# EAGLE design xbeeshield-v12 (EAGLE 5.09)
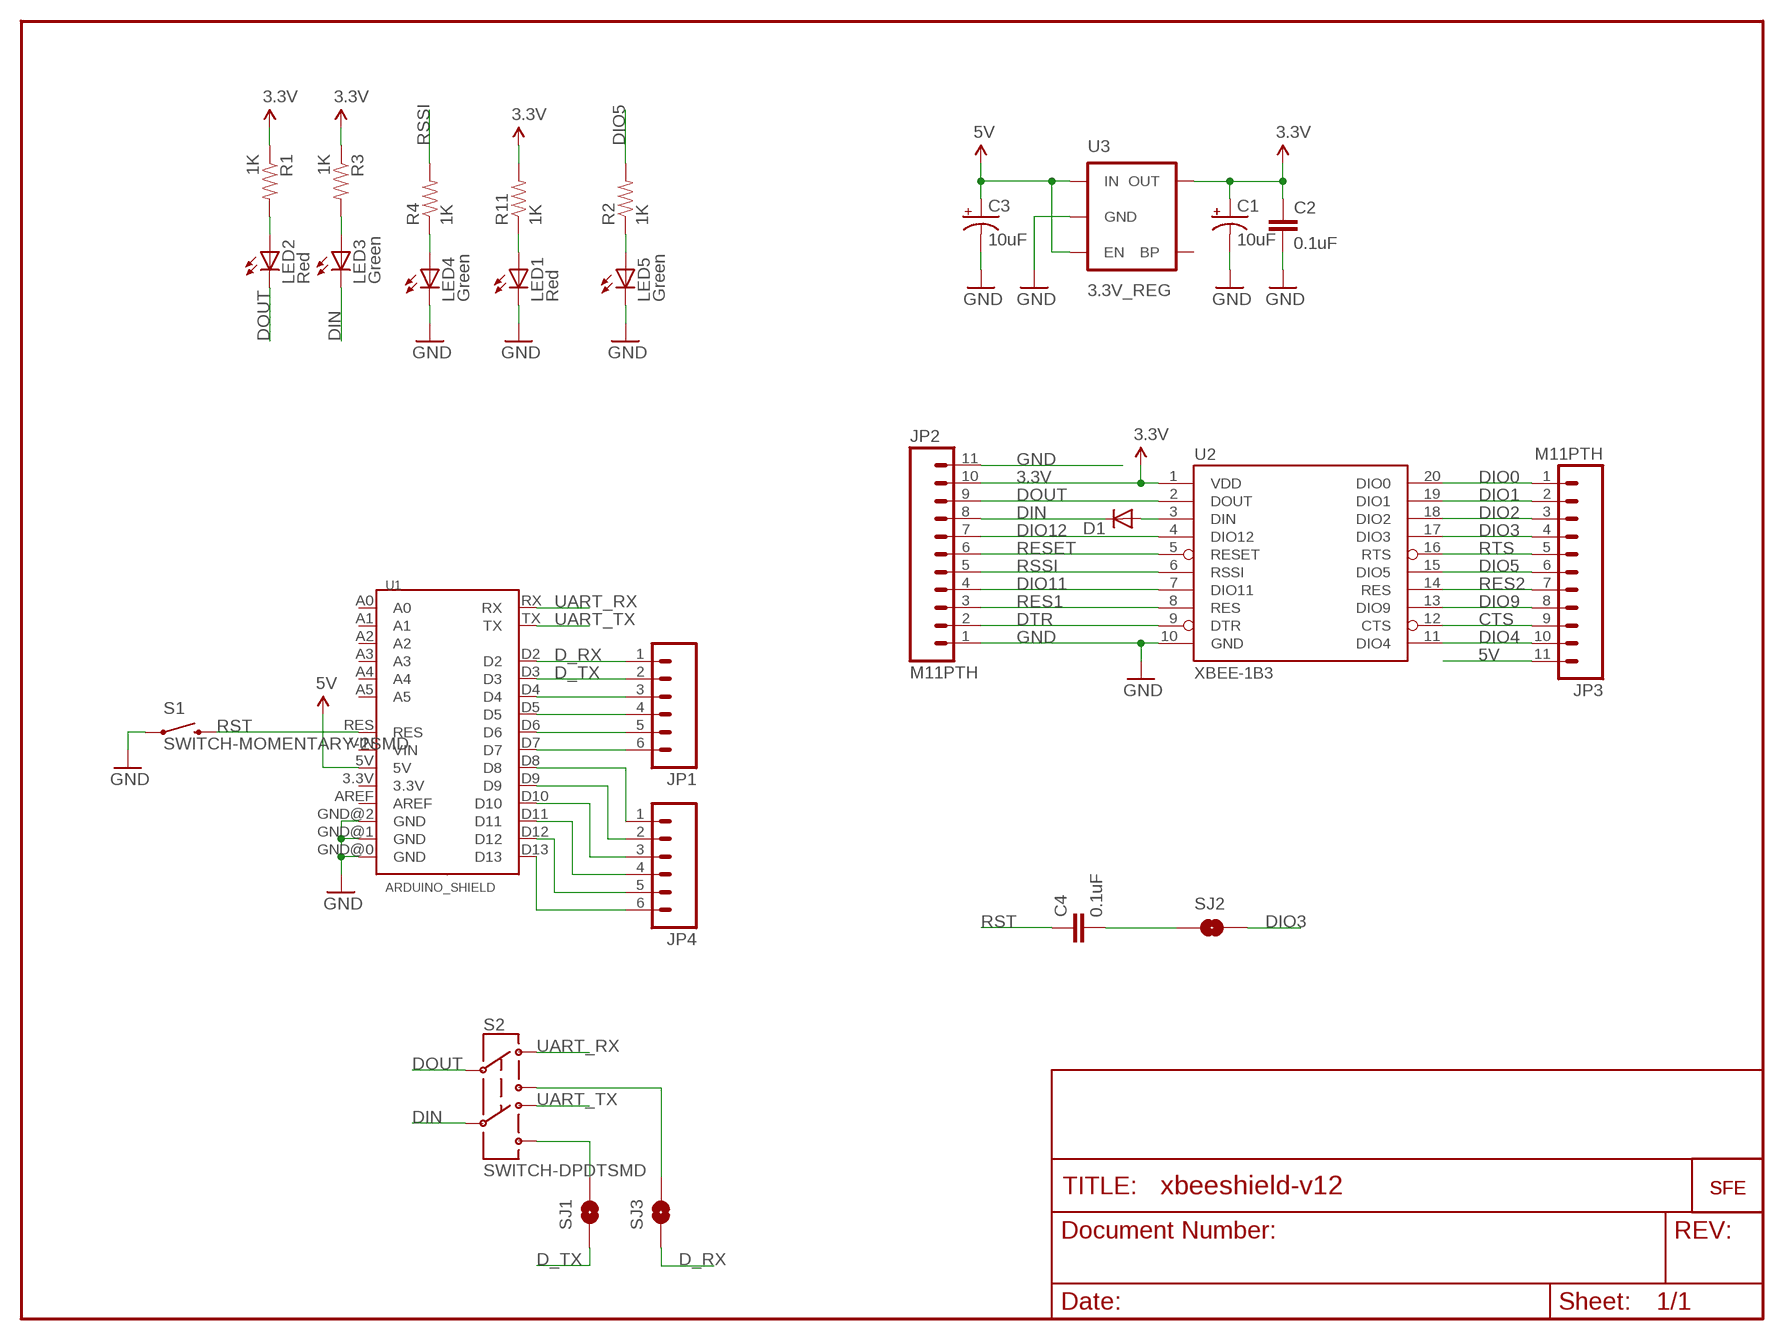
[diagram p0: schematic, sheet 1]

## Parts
C1  10uF  CAP_POL1206  [EIA3216]
C2  0.1uF  CAP0402-CAP  [0402-CAP]
C3  10uF  CAP_POL1206  [EIA3216]
C4  0.1uF  CAP0402-CAP  [0402-CAP]
D1  DIODESOD  [SOD-323]
JP1  M06SIP  [1X06]
JP2  M11PTH  [1X11]
JP3  M11PTH  [1X11]
JP4  M06SIP  [1X06]
LED1  Red  LED0603  [LED-0603]
LED2  Red  LED0603  [LED-0603]
LED3  Green  LED0603  [LED-0603]
LED4  Green  LED0603  [LED-0603]
LED5  Green  LED0603  [LED-0603]
R1  1K  RESISTOR0402-RES  [0402-RES]
R2  1K  RESISTOR0402-RES  [0402-RES]
R3  1K  RESISTOR0402-RES  [0402-RES]
R4  1K  RESISTOR0402-RES  [0402-RES]
R11  1K  RESISTOR0402-RES  [0402-RES]
S1  SWITCH-MOMENTARY-2SMD  [TACTILE_SWITCH_SMD]
S2  SWITCH-DPDTSMD  [AYZ0202]
SJ1  D_TX  SOLDERJUMPERNC  [SJ_2S]
SJ2  SOLDERJUMPERTRACE  [SJ_2S-TRACE]
SJ3  D_RX  SOLDERJUMPERNC  [SJ_2S]
U1  ARDUINO_SHIELD  [DUEMILANOVE_SHIELD]
U2  XBEE-1B3  [XBEE-SMD]
U3  3.3V_REG  V_REG_LDOSMD  [SOT23-5]
U$1  LOGO-SFESK  [SFE-LOGO-FLAME]
U$4  LOGO-SFENEW  [SFE-NEW-WEBLOGO]

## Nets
3.3V: C1.A(+) C2.1 JP2.10 R1.1 R3.1 R11.2 U2.1(VDD) U3.5(OUT)
5V: C3.A(+) JP3.11 U1.5V U3.1(IN) U3.3(EN)
CTS: JP3.9 U2.12(CTS)
D_RX: JP1.1 SJ3.1 U1.D2
D_TX: JP1.2 SJ1.1 U1.D3
DIN: D1.1(C) JP2.8 LED3.C S2.5
DIO0: JP3.1 U2.20(DIO0)
DIO1: JP3.2 U2.19(DIO1)
DIO2: JP3.3 U2.18(DIO2)
DIO3: JP3.4 SJ2.2 U2.17(DIO3)
DIO4: JP3.10 U2.11(DIO4)
DIO5: JP3.6 R2.2 U2.15(DIO5)
DIO9: JP3.8 U2.13(DIO9)
DIO11: JP2.4 U2.7(DIO11)
DIO12: JP2.7 U2.4(DIO12)
DOUT: JP2.9 LED2.C S2.2 U2.2(DOUT)
DTR: JP2.2 U2.9(DTR)
GND: C1.C(-) C2.2 C3.C(-) JP2.1 JP2.11 LED1.C LED4.C LED5.C S1.1 U1.GND@0(GND) U1.GND@1(GND) U1.GND@2(GND) U2.10(GND) U3.2(GND)
N$1: LED2.A R1.2
N$2: LED4.A R4.1
N$3: D1.2(A) U2.3(DIN)
N$4: LED3.A R3.2
N$5: C4.2 SJ2.1
N$17: JP4.1 U1.D8
N$18: JP4.2 U1.D9
N$30: JP4.3 U1.D10
N$38: LED1.A R11.1
N$43: JP4.4 U1.D11
N$55: JP4.5 U1.D12
N$67: JP4.6 U1.D13
N$139: LED5.A R2.1
N$140: S2.6 SJ1.2
N$141: S2.3 SJ3.2
N$142: JP1.3 U1.D4
N$143: JP1.4 U1.D5
N$144: JP1.5 U1.D6
N$145: JP1.6 U1.D7
RES1: JP2.3 U2.8(RES)
RES2: JP3.7 U2.14(RES)
RESET: JP2.6 U2.5(RESET)
RSSI: JP2.5 R4.2 U2.6(RSSI)
RST: C4.1 S1.3 U1.RES
RTS: JP3.5 U2.16(RTS)
UART_RX: S2.1 U1.RX
UART_TX: S2.4 U1.TX
Unconnected: U1.3.3V U1.A0 U1.A1 U1.A2 U1.A3 U1.A4 U1.A5 U1.AREF U1.VIN U3.4(BP)

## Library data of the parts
C1 C3 = SparkFun:CAP_POL: Capacitor Polarized
C2 C4 = SparkFun:CAP: Capacitor
D1 = SparkFun:DIODE: Diode
JP1 JP4 = SparkFun:M06: Header 6 Standard 6-pin 0.1" header. Use with straight break away headers (SKU : PRT-00116), right angle break away headers (PRT-00553), swiss pins (PRT-00743), machine pins (PRT-00117), and female headers (PRT-00115). Molex polarized connector foot print use with SKU : PRT-08094 with associated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
JP2 JP3 = SparkFun:M11: Header 11 Standard 11-pin 0.1" header. Use with straight break away headers (SKU : PRT-00116), right angle break away headers (PRT-00553), swiss pins (PRT-00743), machine pins (PRT-00117), and female headers (PRT-00115).
LED1-LED5 = SparkFun:LED: LEDs
R1-R4 R11 = SparkFun:RESISTOR: Resistor
S1 = SparkFun:SWITCH-MOMENTARY-2
S2 = SparkFun:SWITCH-DPDT: DPDT Version of the COM-00597
SJ1-SJ3 = SparkFun:SOLDERJUMPER: Solder Jumper
U1 = SparkFun:ARDUINO_SHIELD
U2 = SparkFun:XBEE-1
U3 = SparkFun:V_REG_LDO: Voltage Regulator LDO Standard 150mA LDO voltage regulator in SOT-23 layout. Micrel part MIC5205. BP (by-pass) pin is used to lower output noise with 470pF cap.
U$1 U$4 = SparkFun:LOGO-SFE: Spark Fun Electronics PCB Logo

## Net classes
0 default: width 0.203 mm
1 vcc: width 0.305 mm

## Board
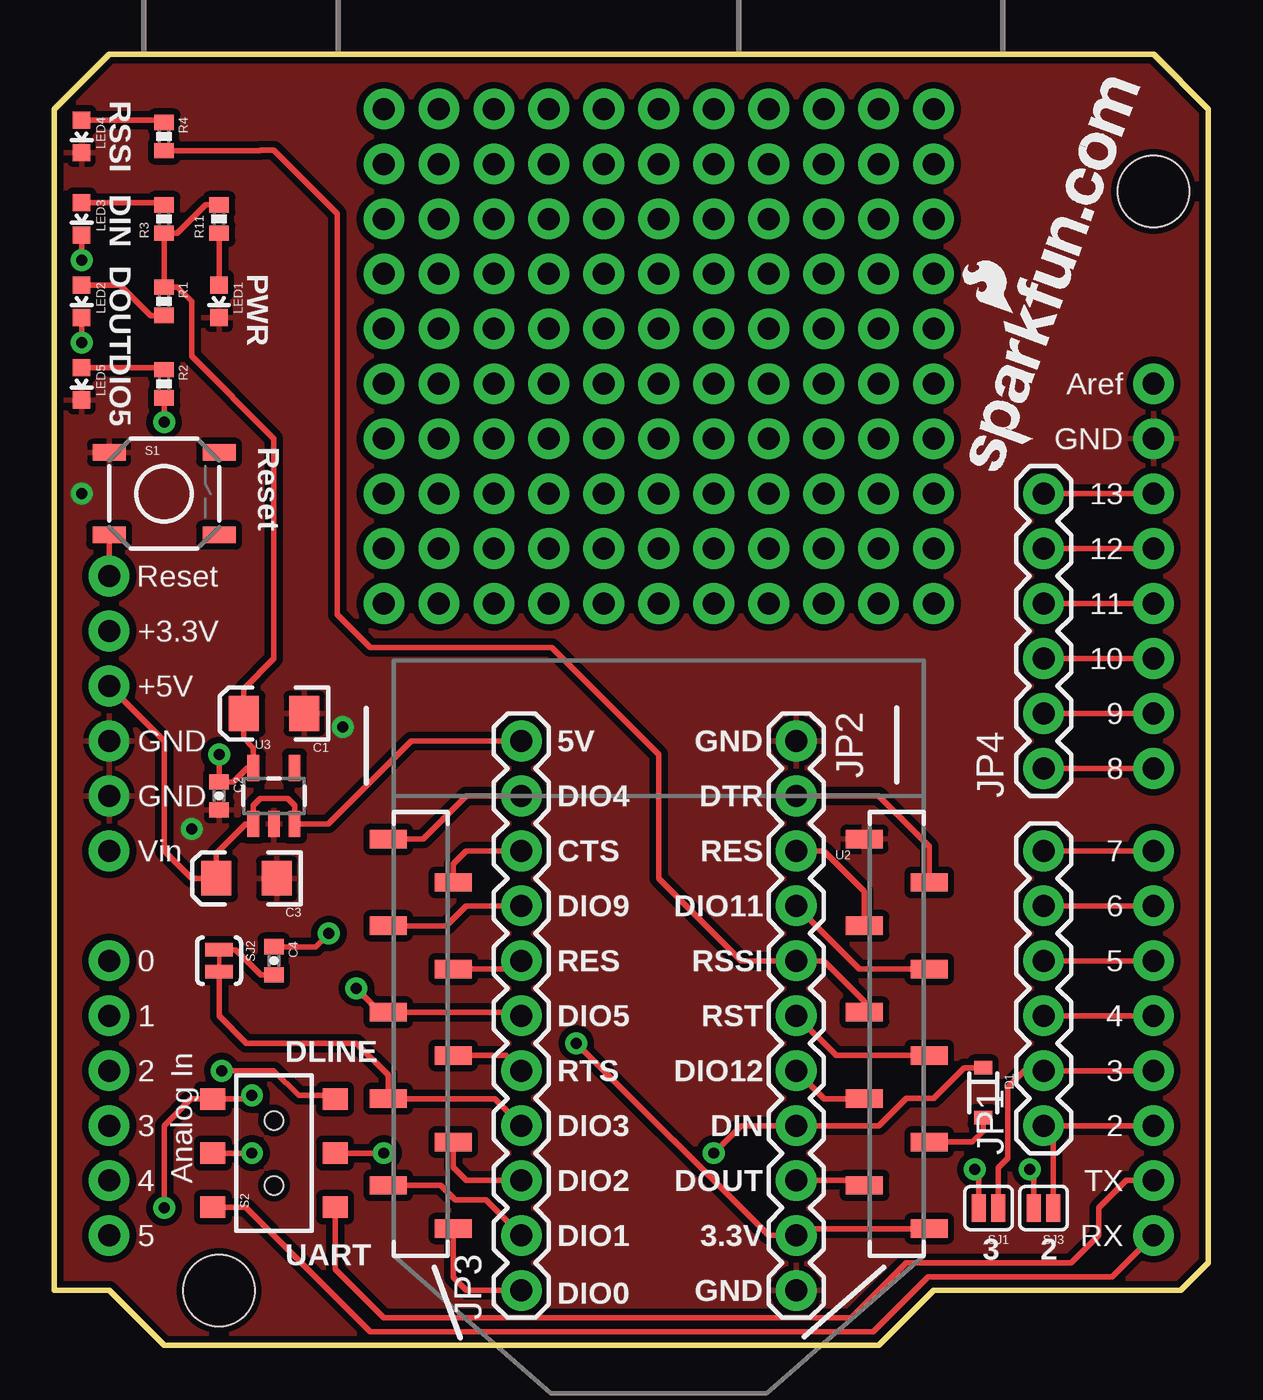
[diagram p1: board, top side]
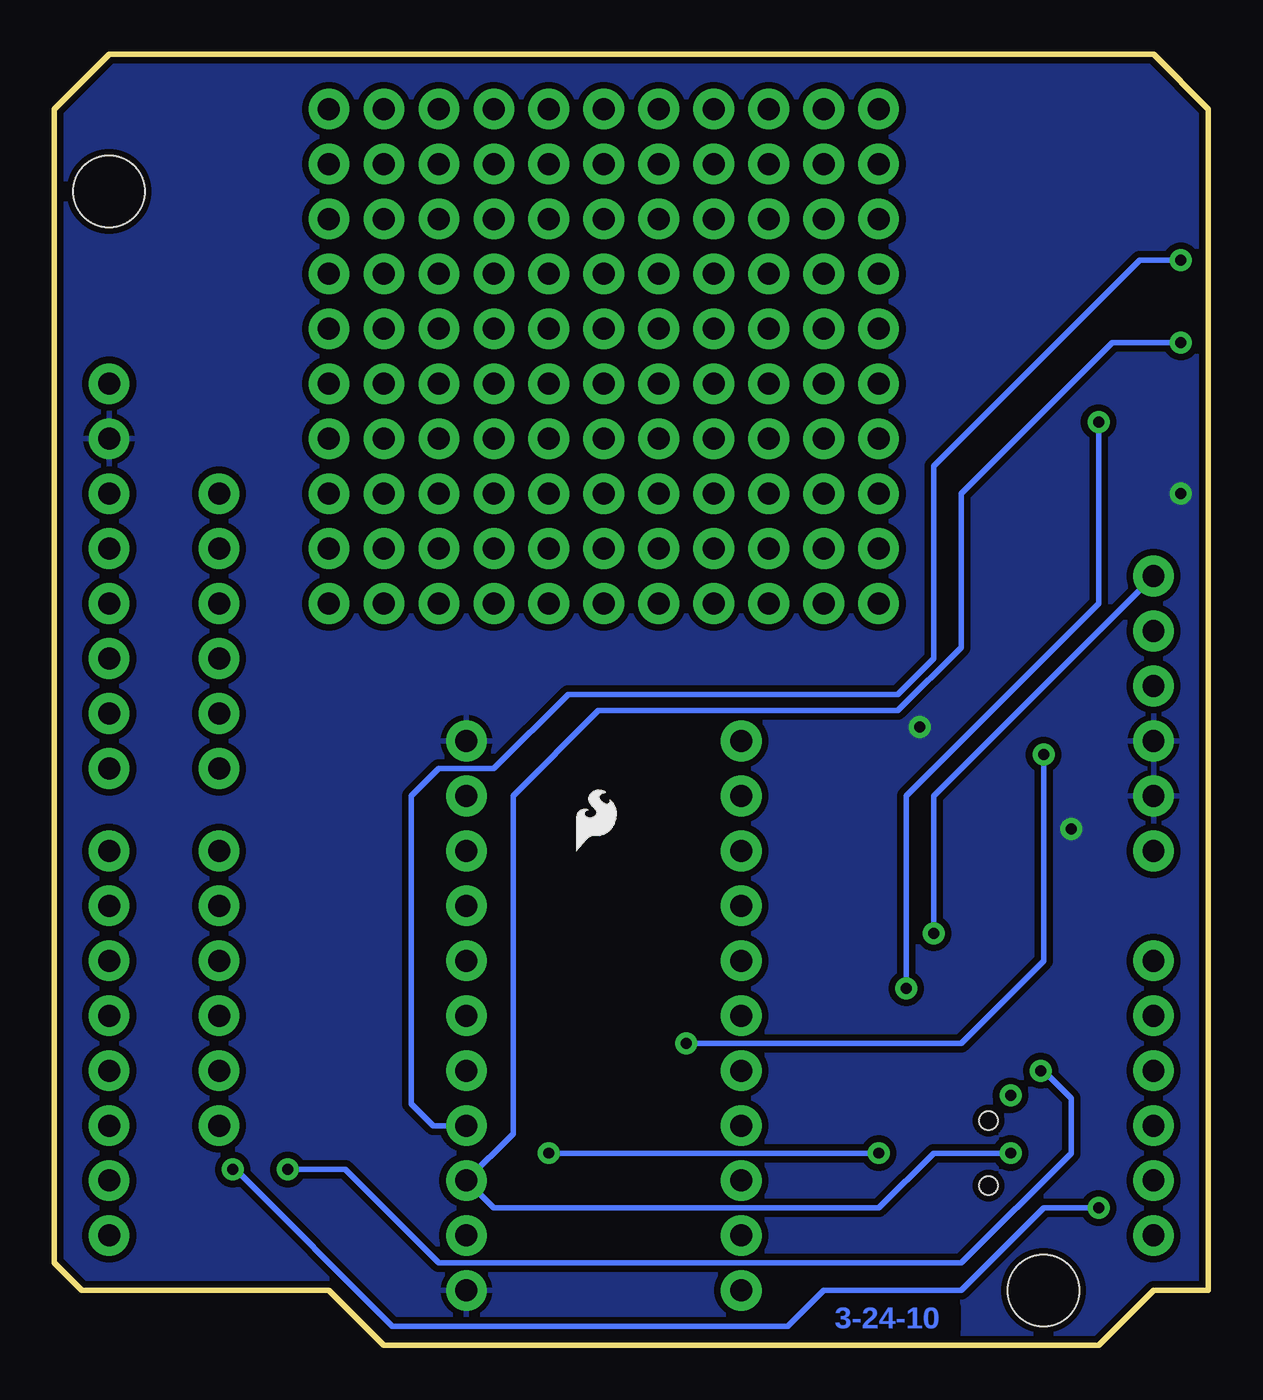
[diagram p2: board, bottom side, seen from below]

Size 53.34 x 59.69 mm. Coordinates in mm from the lower left corner, seen from the top.
Outline: 0,2.54 0,57.15 2.54,59.69 50.8,59.69 53.34,57.15 53.34,3.81 52.07,2.54 40.64,2.54 38.1,0 5.08,0 2.54,2.54 0,2.54
Copper layers (1*16): Top 0.035mm / dielectric 1.5mm / Bottom 0.035mm
Design rules "SparkFun": minimum track width 8mil, minimum drill 20mil, track to track 8mil, track to pad 8mil, pad to pad 8mil, via to via 8mil, smd to smd 8mil, copper to edge 8mil, drill to drill 8mil, minimum pad ring 12mil, minimum via ring 10mil, stop-mask expansion 4mil, vias tented up to drill 20mil, thermal gap 10mil

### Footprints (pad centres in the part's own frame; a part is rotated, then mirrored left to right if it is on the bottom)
EIA3216 = smd 1.4 x 1.6: A 1.4,0; C -1.4,0
0402-CAP = smd 0.7 x 0.9: 1 -0.65,0; 2 0.65,0
SOD-323 = smd 0.63 x 0.83: 1 -1.15,0; 2 1.15,0
1X06 = drill 1.016 pad 1.88 round: 1 0,0; 2 2.54,0; 3 5.08,0; 4 7.62,0; 5 10.16,0; 6 12.7,0
1X11 = drill 1.016 pad 1.88 round: 1 0,0; 2 2.54,0; 3 5.08,0; 4 7.62,0; 5 10.16,0; 6 12.7,0; 7 15.24,0; 8 17.78,0; 9 20.32,0; 10 22.86,0; 11 25.4,0
LED-0603 = smd 0.8 x 0.8: A 0,-0.75; C 0,0.75
0402-RES = smd 0.7 x 0.9: 1 -0.65,0; 2 0.65,0
TACTILE_SWITCH_SMD = smd 1.524 x 0.762: 1 -2.54,1.905; 2 2.54,1.905; 3 -2.54,-1.905; 4 2.54,-1.905
AYZ0202 = smd 1 x 1.15: 1 -2.5,2.825; 2 0,2.825; 3 2.5,2.825; 4 -2.5,-2.825; 5 0,-2.825; 6 2.5,-2.825 | hole 0.85: 1.5,0; -1.5,0
SJ_2S = smd 0.635 x 1.27: 1 -0.45,0; 2 0.45,0
SJ_2S-TRACE = smd 0.635 x 1.27: 1 -0.508,0; 2 0.508,0
DUEMILANOVE_SHIELD = drill 1.016 pad 1.88 round: 3.3V 50.8,26.67; 5V 50.8,29.21; A0 50.8,41.91; A1 50.8,44.45; A2 50.8,46.99; A3 50.8,49.53; A4 50.8,52.07; A5 50.8,54.61; AREF 2.54,15.24; D2 2.54,49.53; D3 2.54,46.99; D4 2.54,44.45; D5 2.54,41.91; D6 2.54,39.37; D7 2.54,36.83; D8 2.54,33.02; D9 2.54,30.48; D10 2.54,27.94; D11 2.54,25.4; D12 2.54,22.86; D13 2.54,20.32; GND@0 50.8,31.75; GND@1 50.8,34.29; GND@2 2.54,17.78; RES 50.8,24.13; RX 2.54,54.61; TX 2.54,52.07; VIN 50.8,36.83 | hole 3.302: 45.72,57.15; 2.54,6.35
XBEE-SMD = smd 1.7 x 0.85: 1 -12.5,20; 2 -9.5,18; 3 -12.5,16; 4 -9.5,14; 5 -12.5,12; 6 -9.5,10; 7 -12.5,8; 8 -9.5,6; 9 -12.5,4; 10 -9.5,2; 11 12.5,2; 12 9.5,4; 13 12.5,6; 14 9.5,8; 15 12.5,10; 16 9.5,12; 17 12.5,14; 18 9.5,16; 19 12.5,18; 20 9.5,20
SOT23-5 = smd 0.55 x 1.2: 1 -0.95,-1.3; 2 0,-1.3; 3 0.95,-1.3; 4 0.95,1.3; 5 -0.95,1.3

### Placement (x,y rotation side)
C1  10.16,29.21 180 top
C2  7.62,25.4 270 top
C3  8.89,21.59 180 top
C4  10.16,17.78 270 top
D1  42.93,11.68 270 top
JP1  45.72,10.16 90 top
JP2  34.29,27.94 270 top
JP3  21.59,2.54 90 top
JP4  45.72,26.67 90 top
LED1  7.62,48.26 180 top
LED2  1.27,48.26 180 top
LED3  1.27,52.07 180 top
LED4  1.27,55.88 180 top
LED5  1.27,44.45 180 top
R1  5.08,48.26 270 top
R2  5.08,44.45 270 top
R3  5.08,52.07 90 top
R4  5.08,55.88 270 top
R11  7.62,52.07 90 top
S1  5.08,39.37 0 top
S2  10.16,8.89 90 top
SJ1  43.18,6.35 180 top
SJ2  7.62,17.78 270 top
SJ3  45.72,6.35 180 top
U1  53.34,59.69 180 top
U2  27.94,25.4 180 top
U3  10.16,25.4 0 top
U$1  29.21,22.86 0 bottom
U$4  44.54,39.97 70 top

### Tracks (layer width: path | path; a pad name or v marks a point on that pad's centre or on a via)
3.3V  (via drill 0.51)
  Top 0.254: R11.2 7,52.72 5.7,51.42 R3.1 R1.1 5.7,48.91 6.35,48.26 6.35,45.72 10.16,41.91 10.16,31.75 8.76,30.35 C1.A 8.76,28.07 9.21,27.62 U3.5 8.92,26.7 8.27,26.05 C2.1 v7.62,27.3 | U2.1 34.61,5.4 JP2.10 33.02,5.08 v24.13,13.97
  Bottom 0.254: v24.13,13.97 11.43,13.97 7.62,17.78 v7.62,27.3
5V
  Top 0.254: U1.5V 5.08,27.94 5.08,22.86 6.35,21.59 C3.A 7.49,22.73 8.86,24.1 U3.1 9.21,24.96 9.53,25.27 10.79,25.27 11.11,24.96 U3.3 12.67,24.1 16.51,27.94 JP3.11
CTS
  Top 0.254: U2.12 18.44,22.25 19.05,22.86 JP3.9
D_RX
  Top 0.254: U1.D2 JP1.1 46.17,9.71 SJ3.1
D_TX
  Top 0.254: U1.D3 JP1.2 44.83,12.7 44.07,11.94 44.07,8.64 43.63,8.2 SJ1.1
DIN  (via drill 0.51)
  Top 0.254: v1.27,50.16 LED3.C | D1.1 42.04,12.83 40.64,11.43 39.37,11.43 38.1,10.16 JP2.8 31.75,10.16 v30.48,8.89 | S2.5 v15.24,8.89
  Bottom 0.254: v1.27,50.16 3.17,50.16 12.7,40.64 12.7,31.75 14.35,30.1 29.59,30.1 33.02,26.67 35.56,26.67 36.83,25.4 36.83,11.18 35.81,10.16 JP2.8 | v15.24,8.89 v30.48,8.89
DIO0
  Top 0.254: U2.20 18.44,3.15 19.05,2.54 JP3.1
DIO1
  Top 0.254: JP3.2 19.94,6.73 18.54,6.73 17.87,7.4 U2.19
DIO2
  Top 0.254: U2.18 18.44,8.23 19.05,7.62 JP3.3
DIO3
  Top 0.254: JP3.4 20.35,11.4 U2.17 15.44,12.5 13.97,13.97 8.89,13.97 7.62,15.24 SJ2.2
DIO4
  Top 0.254: U2.11 17.05,23.4 19.05,25.4 JP3.10
DIO5  (via drill 0.51)
  Top 0.254: v5.08,42.67 R2.2 | JP3.6 21.43,15.4 U2.15 15.08,15.4 v13.97,16.51
  Bottom 0.254: v13.97,16.51 13.97,25.4 5.08,34.29 v5.08,42.67
DIO9
  Top 0.254: U2.13 18.13,19.4 19.05,20.32 JP3.8
DIO11
  Top 0.254: U2.7 37.21,17.4 JP2.4
DIO12
  Top 0.254: U2.4 35.59,11.4 JP2.7
DOUT  (via drill 0.51)
  Top 0.254: v1.27,46.35 LED2.C | JP2.9 37.22,7.62 U2.2 | S2.2 v9.14,8.89
  Bottom 0.254: v1.27,46.35 4.45,46.35 11.43,39.37 11.43,32.26 14.35,29.34 28.19,29.34 32.13,25.4 32.13,9.78 JP2.9 33.02,6.35 15.24,6.35 12.7,8.89 v9.14,8.89
DTR
  Top 0.254: JP2.2 38.1,25.4 40.44,23.06 U2.9
GND  (via drill 0.51)
  other vias: 1.27,39.37 6.35,23.88 13.34,28.57
  pour Top (isolate 0.305): 0,0 0,59.69 53.34,59.69 53.34,0
  pour Bottom (isolate 0.305): 0,59.69 0,0 53.34,0 53.34,59.69
N$1
  Top 0.254: LED2.A 3.06,49.01 4.46,47.61 R1.2
N$2
  Top 0.254: LED4.A 4.98,56.63 R4.1
N$3
  Top 0.254: U2.3 42.42,9.4 42.93,9.91 D1.2
N$4
  Top 0.254: LED3.A 4.98,52.82 R3.2
N$5
  Top 0.254: C4.2 9.54,17.13 8.38,18.29 SJ2.1
N$17
  Top 0.254: JP4.1 U1.D8
N$18
  Top 0.254: JP4.2 U1.D9
N$19  (via drill 1.02 pad 1.88)
  other vias: 40.64,34.29
N$20  (via drill 1.02 pad 1.88)
  other vias: 38.1,34.29
N$21  (via drill 1.02 pad 1.88)
  other vias: 35.56,34.29
N$22  (via drill 1.02 pad 1.88)
  other vias: 33.02,34.29
N$23  (via drill 1.02 pad 1.88)
  other vias: 30.48,34.29
N$24  (via drill 1.02 pad 1.88)
  other vias: 27.94,34.29
N$25  (via drill 1.02 pad 1.88)
  other vias: 25.4,34.29
N$26  (via drill 1.02 pad 1.88)
  other vias: 22.86,34.29
N$27  (via drill 1.02 pad 1.88)
  other vias: 20.32,34.29
N$28  (via drill 1.02 pad 1.88)
  other vias: 17.78,34.29
N$29  (via drill 1.02 pad 1.88)
  other vias: 15.24,34.29
N$30
  Top 0.254: JP4.3 U1.D10
N$31  (via drill 1.02 pad 1.88)
  other vias: 40.64,36.83
N$32  (via drill 1.02 pad 1.88)
  other vias: 38.1,36.83
N$33  (via drill 1.02 pad 1.88)
  other vias: 35.56,36.83
N$34  (via drill 1.02 pad 1.88)
  other vias: 33.02,36.83
N$35  (via drill 1.02 pad 1.88)
  other vias: 30.48,36.83
N$36  (via drill 1.02 pad 1.88)
  other vias: 27.94,36.83
N$37  (via drill 1.02 pad 1.88)
  other vias: 25.4,36.83
N$38
  Top 0.254: LED1.A R11.1
N$39  (via drill 1.02 pad 1.88)
  other vias: 22.86,36.83
N$40  (via drill 1.02 pad 1.88)
  other vias: 20.32,36.83
N$41  (via drill 1.02 pad 1.88)
  other vias: 17.78,36.83
N$42  (via drill 1.02 pad 1.88)
  other vias: 15.24,36.83
N$43
  Top 0.254: JP4.4 U1.D11
N$44  (via drill 1.02 pad 1.88)
  other vias: 40.64,39.37
N$45  (via drill 1.02 pad 1.88)
  other vias: 38.1,39.37
N$46  (via drill 1.02 pad 1.88)
  other vias: 35.56,39.37
N$47  (via drill 1.02 pad 1.88)
  other vias: 33.02,39.37
N$48  (via drill 1.02 pad 1.88)
  other vias: 30.48,39.37
N$49  (via drill 1.02 pad 1.88)
  other vias: 27.94,39.37
N$50  (via drill 1.02 pad 1.88)
  other vias: 25.4,39.37
N$51  (via drill 1.02 pad 1.88)
  other vias: 22.86,39.37
N$52  (via drill 1.02 pad 1.88)
  other vias: 20.32,39.37
N$53  (via drill 1.02 pad 1.88)
  other vias: 17.78,39.37
N$54  (via drill 1.02 pad 1.88)
  other vias: 15.24,39.37
N$55
  Top 0.254: JP4.5 U1.D12
N$56  (via drill 1.02 pad 1.88)
  other vias: 40.64,41.91
N$57  (via drill 1.02 pad 1.88)
  other vias: 38.1,41.91
N$58  (via drill 1.02 pad 1.88)
  other vias: 35.56,41.91
N$59  (via drill 1.02 pad 1.88)
  other vias: 33.02,41.91
N$60  (via drill 1.02 pad 1.88)
  other vias: 30.48,41.91
N$61  (via drill 1.02 pad 1.88)
  other vias: 27.94,41.91
N$62  (via drill 1.02 pad 1.88)
  other vias: 25.4,41.91
N$63  (via drill 1.02 pad 1.88)
  other vias: 22.86,41.91
N$64  (via drill 1.02 pad 1.88)
  other vias: 20.32,41.91
N$65  (via drill 1.02 pad 1.88)
  other vias: 17.78,41.91
N$66  (via drill 1.02 pad 1.88)
  other vias: 15.24,41.91
N$67
  Top 0.254: JP4.6 U1.D13
N$68  (via drill 1.02 pad 1.88)
  other vias: 40.64,44.45
N$69  (via drill 1.02 pad 1.88)
  other vias: 38.1,44.45
N$70  (via drill 1.02 pad 1.88)
  other vias: 35.56,44.45
N$71  (via drill 1.02 pad 1.88)
  other vias: 33.02,44.45
N$72  (via drill 1.02 pad 1.88)
  other vias: 30.48,44.45
N$73  (via drill 1.02 pad 1.88)
  other vias: 27.94,44.45
N$74  (via drill 1.02 pad 1.88)
  other vias: 25.4,44.45
N$75  (via drill 1.02 pad 1.88)
  other vias: 22.86,44.45
N$76  (via drill 1.02 pad 1.88)
  other vias: 20.32,44.45
N$77  (via drill 1.02 pad 1.88)
  other vias: 17.78,44.45
N$78  (via drill 1.02 pad 1.88)
  other vias: 15.24,44.45
N$80  (via drill 1.02 pad 1.88)
  other vias: 40.64,46.99
N$81  (via drill 1.02 pad 1.88)
  other vias: 38.1,46.99
N$82  (via drill 1.02 pad 1.88)
  other vias: 35.56,46.99
N$83  (via drill 1.02 pad 1.88)
  other vias: 33.02,46.99
N$84  (via drill 1.02 pad 1.88)
  other vias: 30.48,46.99
N$85  (via drill 1.02 pad 1.88)
  other vias: 27.94,46.99
N$86  (via drill 1.02 pad 1.88)
  other vias: 25.4,46.99
N$87  (via drill 1.02 pad 1.88)
  other vias: 22.86,46.99
N$88  (via drill 1.02 pad 1.88)
  other vias: 20.32,46.99
N$89  (via drill 1.02 pad 1.88)
  other vias: 17.78,46.99
N$90  (via drill 1.02 pad 1.88)
  other vias: 15.24,46.99
N$92  (via drill 1.02 pad 1.88)
  other vias: 40.64,49.53
N$93  (via drill 1.02 pad 1.88)
  other vias: 38.1,49.53
N$94  (via drill 1.02 pad 1.88)
  other vias: 35.56,49.53
N$95  (via drill 1.02 pad 1.88)
  other vias: 33.02,49.53
N$96  (via drill 1.02 pad 1.88)
  other vias: 30.48,49.53
N$97  (via drill 1.02 pad 1.88)
  other vias: 27.94,49.53
N$98  (via drill 1.02 pad 1.88)
  other vias: 25.4,49.53
N$99  (via drill 1.02 pad 1.88)
  other vias: 22.86,49.53
N$100  (via drill 1.02 pad 1.88)
  other vias: 20.32,49.53
N$101  (via drill 1.02 pad 1.88)
  other vias: 17.78,49.53
N$102  (via drill 1.02 pad 1.88)
  other vias: 15.24,49.53
N$104  (via drill 1.02 pad 1.88)
  other vias: 40.64,52.07
N$105  (via drill 1.02 pad 1.88)
  other vias: 38.1,52.07
N$106  (via drill 1.02 pad 1.88)
  other vias: 35.56,52.07
N$107  (via drill 1.02 pad 1.88)
  other vias: 33.02,52.07
N$108  (via drill 1.02 pad 1.88)
  other vias: 30.48,52.07
N$109  (via drill 1.02 pad 1.88)
  other vias: 27.94,52.07
N$110  (via drill 1.02 pad 1.88)
  other vias: 25.4,52.07
N$111  (via drill 1.02 pad 1.88)
  other vias: 22.86,52.07
N$112  (via drill 1.02 pad 1.88)
  other vias: 20.32,52.07
N$113  (via drill 1.02 pad 1.88)
  other vias: 17.78,52.07
N$114  (via drill 1.02 pad 1.88)
  other vias: 15.24,52.07
N$116  (via drill 1.02 pad 1.88)
  other vias: 40.64,54.61
N$117  (via drill 1.02 pad 1.88)
  other vias: 38.1,54.61
N$118  (via drill 1.02 pad 1.88)
  other vias: 35.56,54.61
N$119  (via drill 1.02 pad 1.88)
  other vias: 33.02,54.61
N$120  (via drill 1.02 pad 1.88)
  other vias: 30.48,54.61
N$121  (via drill 1.02 pad 1.88)
  other vias: 27.94,54.61
N$122  (via drill 1.02 pad 1.88)
  other vias: 25.4,54.61
N$123  (via drill 1.02 pad 1.88)
  other vias: 22.86,54.61
N$124  (via drill 1.02 pad 1.88)
  other vias: 20.32,54.61
N$125  (via drill 1.02 pad 1.88)
  other vias: 17.78,54.61
N$126  (via drill 1.02 pad 1.88)
  other vias: 15.24,54.61
N$128  (via drill 1.02 pad 1.88)
  other vias: 40.64,57.15
N$129  (via drill 1.02 pad 1.88)
  other vias: 38.1,57.15
N$130  (via drill 1.02 pad 1.88)
  other vias: 35.56,57.15
N$131  (via drill 1.02 pad 1.88)
  other vias: 33.02,57.15
N$132  (via drill 1.02 pad 1.88)
  other vias: 30.48,57.15
N$133  (via drill 1.02 pad 1.88)
  other vias: 27.94,57.15
N$134  (via drill 1.02 pad 1.88)
  other vias: 25.4,57.15
N$135  (via drill 1.02 pad 1.88)
  other vias: 22.86,57.15
N$136  (via drill 1.02 pad 1.88)
  other vias: 20.32,57.15
N$137  (via drill 1.02 pad 1.88)
  other vias: 17.78,57.15
N$138  (via drill 1.02 pad 1.88)
  other vias: 15.24,57.15
N$139
  Top 0.254: LED5.A 4.98,45.2 R2.1
N$140  (via drill 0.51)
  Top 0.254: S2.6 12.83,11.55 11.31,11.55 10.16,12.7 v7.75,12.7 | SJ1.2 42.73,7.94 v42.55,8.13
  Bottom 0.254: v42.55,8.13 39.88,8.13 35.56,3.81 11.43,3.81 6.35,8.89 6.35,11.43 7.62,12.7 v7.75,12.7
N$141  (via drill 0.51)
  Top 0.254: v9.14,11.56 8.98,11.39 S2.3 6.31,11.39 5.08,10.16 v5.08,6.35 | SJ3.2 45.27,7.94 v45.09,8.13
  Bottom 0.254: v45.09,8.13 44.96,8.13 37.72,0.89 19.43,0.89 17.78,2.54 11.43,2.54 7.62,6.35 v5.08,6.35
N$142
  Top 0.254: JP1.3 U1.D4
N$143
  Top 0.254: JP1.4 U1.D5
N$144
  Top 0.254: JP1.5 U1.D6
N$145
  Top 0.254: JP1.6 U1.D7
RES1
  Top 0.254: JP2.3 35.56,22.86 37.44,20.98 U2.8
RES2
  Top 0.254: U2.14 21.21,17.4 JP3.7
RESET
  Top 0.254: U2.5 36.13,13.4 JP2.6
RSSI
  Top 0.254: U2.6 37.44,15.9 35.56,17.78 JP2.5 31.75,17.78 27.94,21.59 27.94,27.3 22.99,32.26 14.61,32.26 13.08,33.78 13.08,52.32 10.16,55.24 9.53,55.24 9.51,55.23 R4.2
RST  (via drill 0.51)
  Top 0.254: U1.RES S1.3 | C4.1 12.08,18.43 v12.7,19.05
  Bottom 0.254: U1.RES 12.7,25.4 v12.7,19.05
RTS
  Top 0.254: U2.16 20.89,13.4 JP3.5
UART_RX
  Top 0.254: S2.1 8.85,6.39 14.61,0.64 37.85,0.64 40.39,3.17 48.9,3.17 U1.RX
UART_TX
  Top 0.254: S2.4 12.98,3.52 15.24,1.27 36.83,1.27 39.37,3.81 46.99,3.81 48.26,5.08 48.26,6.35 49.53,7.62 U1.TX

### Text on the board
Bottom: 3-24-10
tPlace: RSSI | DIN | DOUT | PWR | DIO5 | Reset | GND | 5V | DTR | DIO4 | RES | CTS | DIO11 | DIO9 | RSSI | RES | RST | DIO5 | DLINE | DIO12 | RTS | DIN | DIO3 | DOUT | DIO2 | 3.3V | DIO1 | 3 | 2 | UART | GND | DIO0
